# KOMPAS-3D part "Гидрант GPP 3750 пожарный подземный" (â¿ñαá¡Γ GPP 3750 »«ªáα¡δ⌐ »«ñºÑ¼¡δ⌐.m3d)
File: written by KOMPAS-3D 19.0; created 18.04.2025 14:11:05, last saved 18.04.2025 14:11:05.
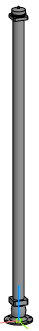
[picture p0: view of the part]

Document properties: Полное имя файла: E:\Dendor Работа Сачек\3D для проекитирвщиков\11.1 Тип GPP. Гидрант пожарный подземный\stp_Тип GPP. 750-6000 Гидрант пожарный подземный\Гидрант GPP 3750 пожарный подземный.m3d

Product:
- Part/product: Гидрант GPP 3750 пожарный подземный

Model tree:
1. Операция без истории:1  (labels: Гидрант GPP 3750 пожарный подземный)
